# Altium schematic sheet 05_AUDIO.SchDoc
size A2; ApprovedBy: DNP; CheckedBy: DNP; Author: DNP; CompanyName: Google LLC; DrawnBy: DNP; Engineer: Bangfei/Michael/Leo; Organization: Google LLC; Address1: 1600 Amphitheatre Parkway; Address2: Mountain View, CA 94043; Address3: DNP; Address4: DNP; DocumentNumber: DNP; Revision: PVT; SheetNumber: 5; SheetTotal: 11; VersionControl_RevNumber: DNP; IsUserConfigurable: DNP
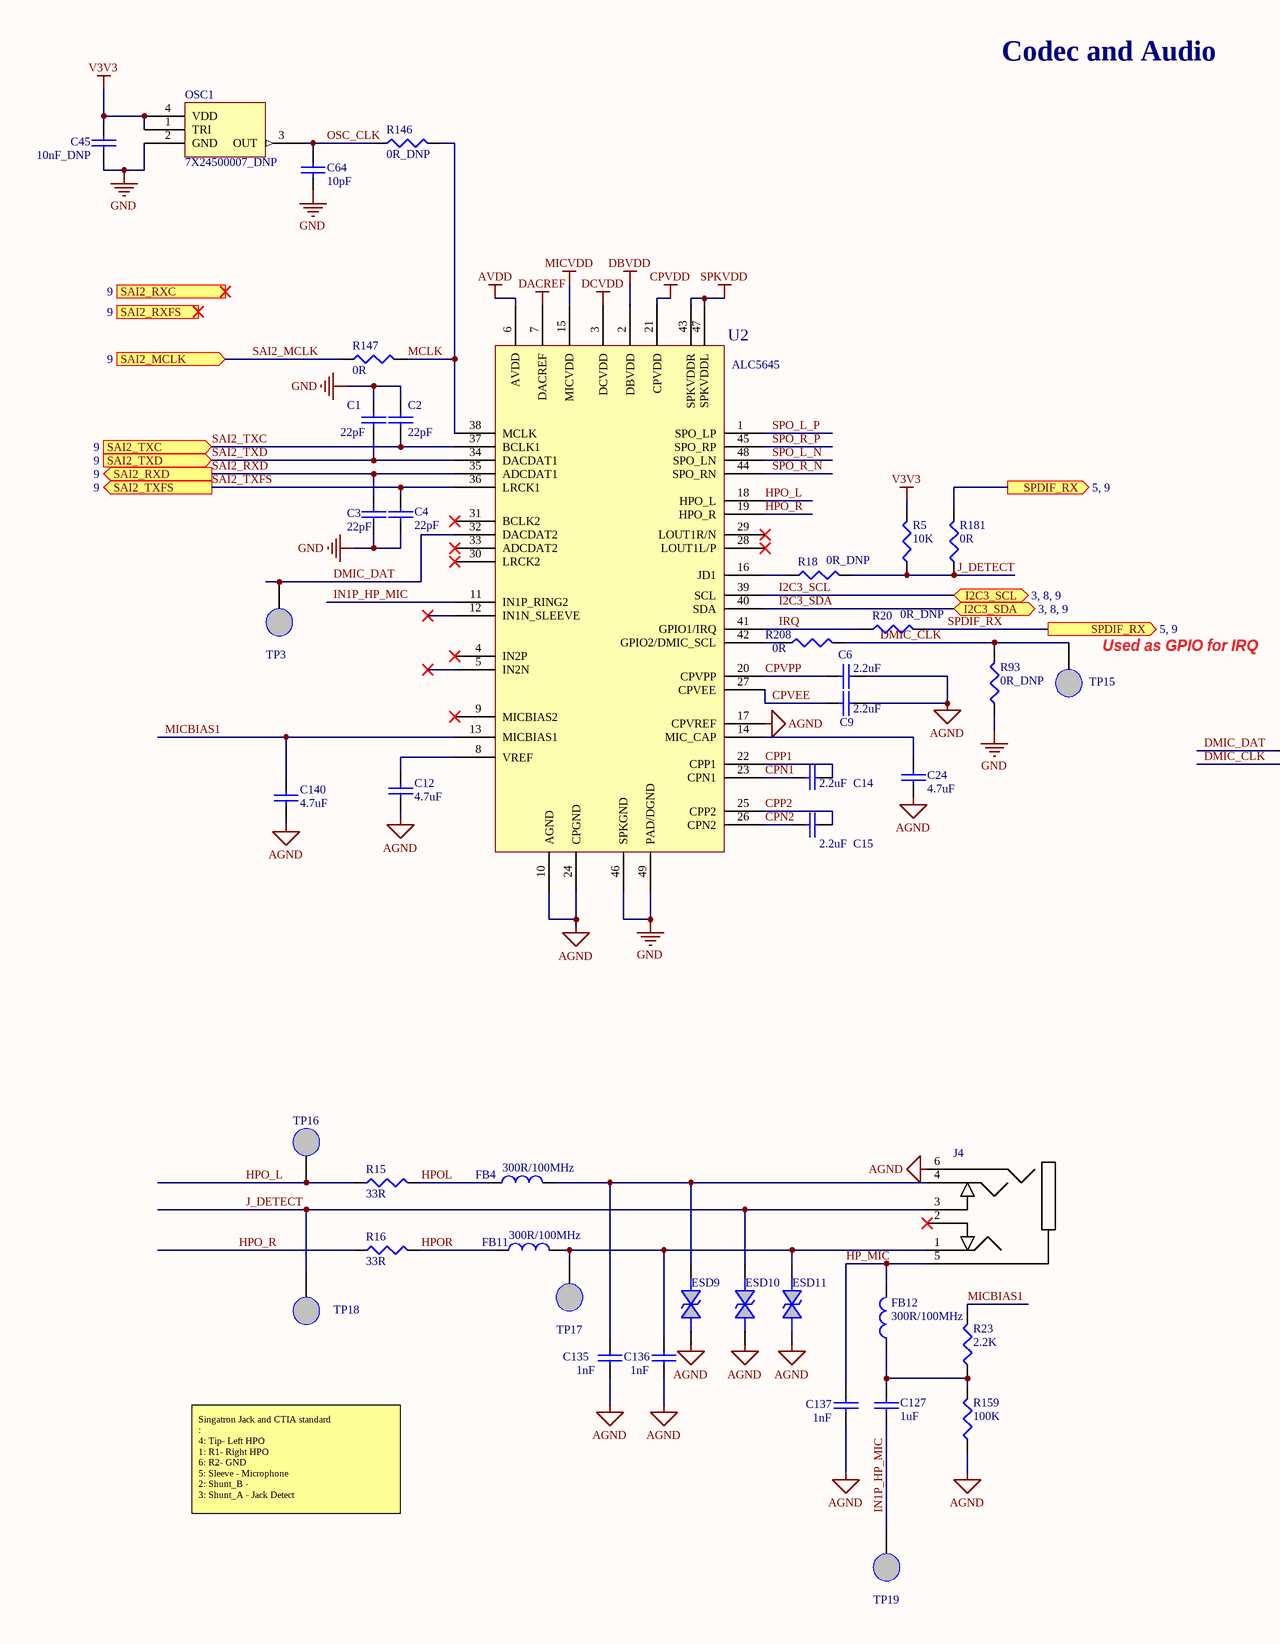
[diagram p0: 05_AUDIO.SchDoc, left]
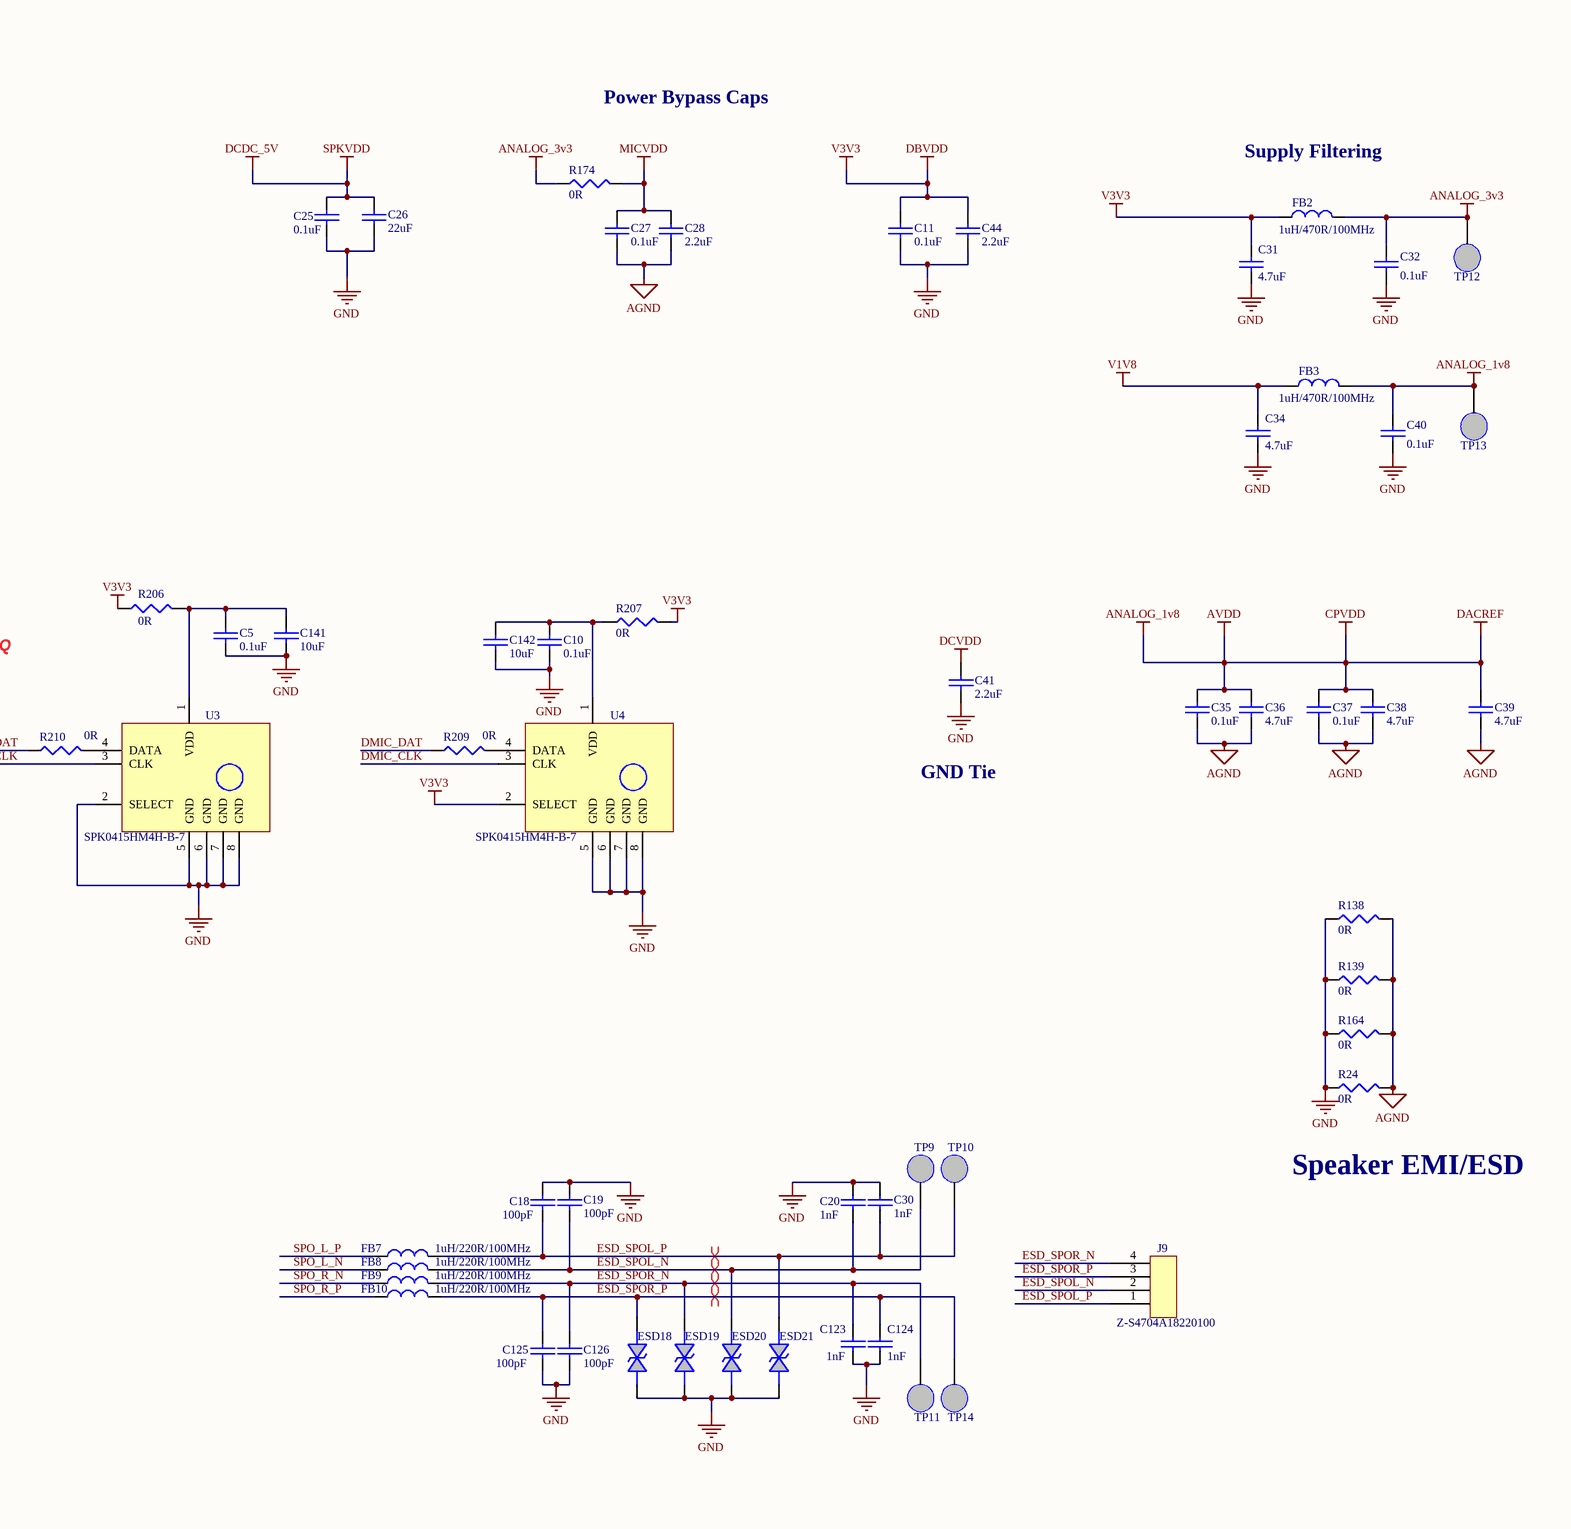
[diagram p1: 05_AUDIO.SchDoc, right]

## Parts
C1  value 22pF  [0201]  (hidden comment: 22pF/6.3V)
C2  value 22pF  [0201]  (hidden comment: 22pF/6.3V)
C3  value 22pF  [0201]  (hidden comment: 22pF/6.3V)
C4  value 22pF  [0201]  (hidden comment: 22pF/6.3V)
C5  value 0.1uF  [0201]  (hidden comment: 0.1uF/10V)
C6  value 2.2uF  [0201]  (hidden comment: 2.2uF/6.3V)
C9  value 2.2uF  [0201]  (hidden comment: 2.2uF/6.3V)
C10  value 0.1uF  [0201]  (hidden comment: 0.1uF/10V)
C11  value 0.1uF  [0201]  (hidden comment: 0.1uF/10V)
C12  value 4.7uF  [0402]  (hidden comment: 4.7uF/10V)
C14  value 2.2uF  [0201]  (hidden comment: 2.2uF/6.3V)
C15  value 2.2uF  [0201]  (hidden comment: 2.2uF/6.3V)
C18  value 100pF  [0201]  (hidden comment: 100pF/25V)
C19  value 100pF  [0201]  (hidden comment: 100pF/25V)
C20  value 1nF  [0201]  (hidden comment: 1nF/25V)
C24  value 4.7uF  [0402]  (hidden comment: 4.7uF/10V)
C25  value 0.1uF  [0402]  (hidden comment: 0.1uF/16V)
C26  value 22uF  [0603]  (hidden comment: 10uF/10V)
C27  value 0.1uF  [0201]  (hidden comment: 0.1uF/10V)
C28  value 2.2uF  [0201]  (hidden comment: 2.2uF/6.3V)
C30  value 1nF  [0201]  (hidden comment: 1nF/25V)
C31  value 4.7uF  [0402]  (hidden comment: 4.7uF/10V)
C32  value 0.1uF  [0603]  (hidden comment: 0.1uF/10V)
C34  value 4.7uF  [0402]  (hidden comment: 4.7uF/10V)
C35  value 0.1uF  [0201]  (hidden comment: 0.1uF/10V)
C36  value 4.7uF  [0402]  (hidden comment: 4.7uF/10V)
C37  value 0.1uF  [0201]  (hidden comment: 0.1uF/10V)
C38  value 4.7uF  [0402]  (hidden comment: 4.7uF/10V)
C39  value 4.7uF  [0402]  (hidden comment: 4.7uF/10V)
C40  value 0.1uF  [0402]  (hidden comment: 0.1uF/16V)
C41  value 2.2uF  [0201]  (hidden comment: 2.2uF/6.3V)
C44  value 2.2uF  [0201]  (hidden comment: 2.2uF/6.3V)
C45  10nF_DNP  [0201]
C64  value 10pF  [0201]  (hidden comment: 10pF/25V)
C123  value 1nF  [0201]  (hidden comment: 1nF/25V)
C124  value 1nF  [0201]  (hidden comment: 1nF/25V)
C125  value 100pF  [0201]  (hidden comment: 100pF/25V)
C126  value 100pF  [0201]  (hidden comment: 100pF/25V)
C127  value 1uF  [0402]  (hidden comment: 1uF/6.3V)
C135  value 1nF  [0201]  (hidden comment: 1nF/25V)
C136  value 1nF  [0201]  (hidden comment: 1nF/25V)
C137  value 1nF  [0201]  (hidden comment: 1nF/25V)
C140  value 4.7uF  [0402]  (hidden comment: 4.7uF/10V)
C141  value 10uF  [0402]  (hidden comment: 10uF/10V)
C142  value 10uF  [0402]  (hidden comment: 10uF/10V)
ESD9  3.5pF/5V  [0201]  (value not drawn)
ESD10  3.5pF/5V  [0201]  (value not drawn)
ESD11  3.5pF/5V  [0201]  (value not drawn)
ESD18  3.5pF/5V  [0201]  (value not drawn)
ESD19  3.5pF/5V  [0201]  (value not drawn)
ESD20  3.5pF/5V  [0201]  (value not drawn)
ESD21  3.5pF/5V  [0201]  (value not drawn)
FB2  1uH/470R/100MHz  [0603]
FB3  1uH/470R/100MHz  [0603]
FB4  300R/100MHz  [0402]
FB7  1uH/220R/100MHz  [0603]
FB8  1uH/220R/100MHz  [0603]
FB9  1uH/220R/100MHz  [0603]
FB10  1uH/220R/100MHz  [0603]
FB11  300R/100MHz  [0402]
FB12  300R/100MHz  [0402]
J4  CONN_2SJ2296-000111  [AUDIO-2SJ2296-000111]  (value not drawn)
J9  Z-S4704A18220100  [SIP4-2_54-S4704A18220100]
OSC1  7X24500007_DNP  [4-SMD-OSC]
R5  10K  [0201]
R15  33R  [0402]
R16  33R  [0402]
R18  0R_DNP  [0201]
R20  0R_DNP  [0201]
R23  2.2K  [0201]
R24  0R  [0201]
R93  0R_DNP  [0201]
R138  0R  [0201]
R139  0R  [0201]
R146  0R_DNP  [0201]
R147  0R  [0201]
R159  100K  [0402]
R164  0R  [0201]
R174  0R  [0402]
R181  0R  [0201]
R206  0R  [0201]
R207  0R  [0201]
R208  0R  [0201]
R209  0R  [0201]
R210  0R  [0201]
TP3  TP NM  [TP_SMD]  (value not drawn)  (no BOM)
TP9  TP NM  [TP_SMD]  (value not drawn)  (no BOM)
TP10  TP NM  [TP_SMD]  (value not drawn)  (no BOM)
TP11  TP NM  [TP_SMD]  (value not drawn)  (no BOM)
TP12  TP NM  [TP_SMD]  (value not drawn)  (no BOM)
TP13  TP NM  [TP_SMD]  (value not drawn)  (no BOM)
TP14  TP NM  [TP_SMD]  (value not drawn)  (no BOM)
TP15  TP NM  [TP_SMD]  (value not drawn)  (no BOM)
TP16  TP NM  [TP_SMD]  (value not drawn)  (no BOM)
TP17  TP NM  [TP_SMD]  (value not drawn)  (no BOM)
TP18  TP NM  [TP_SMD]  (value not drawn)  (no BOM)
TP19  TP NM  [TP_SMD]  (value not drawn)  (no BOM)
U2  ALC5645  [CODEC_ALC5645]
U3  SPK0415HM4H-B-7  [Microphone_SPK0415HM4H-B-7]
U4  SPK0415HM4H-B-7  [Microphone_SPK0415HM4H-B-7]

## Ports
I2C3_SCL (bidir, see 3, 8, 9), I2C3_SDA (bidir, see 3, 8, 9), SAI2_MCLK (in, see 9), SAI2_RXC (in, see 9), SAI2_RXD (out, see 9), SAI2_RXFS (in, see 9), SAI2_TXC (in, see 9), SAI2_TXD (in, see 9), SAI2_TXFS (out, see 9), SPDIF_RX (out, see 5, 9)

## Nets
AGND: C6.2 C9.2 C12.2 C24.1 C27.2 C28.2 C35.2 C36.2 C37.2 C38.2 C39.2 C135.1 C136.1 C137.1 C140.2 ESD9.1 ESD10.1 ESD11.1 J4.6(RING_B) R24.2 R138.2 R139.2 R159.1 R164.2 U2.10(AGND) U2.17(CPVREF) U2.24(CPGND)
ANALOG_1v8: C35.1 C36.1 C37.1 C38.1 C39.1 C40.1 FB3.2 TP13.1 U2.6(AVDD) U2.7(DACREF) U2.21(CPVDD)  [also labelled AVDD, CPVDD, DACREF]
ANALOG_3v3: C32.1 FB2.2 R174.1 TP12.1
DBVDD: C11.1 C31.1 C44.1 C45.1 FB2.1 OSC1.1(TRI) OSC1.4(VDD) R5.2 R206.1 R207.2 U2.2(DBVDD) U4.2(SELECT)  [also labelled V3V3]
DCDC_5V: C25.1 C26.1 U2.43(SPKVDDR) U2.47(SPKVDDL)  [also labelled SPKVDD]
DCVDD: C41.1 U2.3(DCVDD)
GND: C1.1 C2.1 C3.2 C4.2 C5.2 C10.2 C11.2 C18.1 C19.1 C20.2 C25.2 C26.2 C30.2 C31.2 C32.2 C34.2 C40.2 C41.2 C44.2 C45.2 C64.2 C123.1 C124.1 C125.2 C126.2 C141.2 C142.2 ESD18.1 ESD19.1 ESD20.1 ESD21.1 OSC1.2(GND) R24.1 R93.1 R138.1 R139.1 R164.1 U2.46(SPKGND) U2.49(PAD/DGND) U3.2(SELECT) U3.5(GND) U3.6(GND) U3.7(GND) U3.8(GND) U4.5(GND) U4.6(GND) U4.7(GND) U4.8(GND)
MICVDD: C27.1 C28.1 R174.2 U2.15(MICVDD)
V1V8: C34.1 FB3.1
CPN1: C14.1 U2.23(CPN1)
CPN2: C15.1 U2.26(CPN2)
CPP1: C14.2 U2.22(CPP1)
CPP2: C15.2 U2.25(CPP2)
CPVEE: C9.1 U2.27(CPVEE)
CPVPP: C6.1 U2.20(CPVPP)
DMIC_CLK: R93.2 R208.2 TP15.1 U3.3(CLK) U4.3(CLK)
DMIC_DAT: R209.1 R210.1 TP3.1 U2.32(DACDAT2)
ESD_SPOL_N: C19.2 C20.1 ESD20.2 FB8.2 J9.2 TP9.1
ESD_SPOL_P: C18.2 C30.1 ESD21.2 FB7.2 J9.1 TP10.1
ESD_SPOR_N: C123.2 C126.1 ESD19.2 FB9.2 J9.4 TP11.1
ESD_SPOR_P: C124.2 C125.1 ESD18.2 FB10.2 J9.3 TP14.1
HP_MIC: C137.2 FB12.2 J4.5(SLEEVE)
HPO_L: R15.1 TP16.1 U2.18(HPO_L)
HPO_R: R16.1 U2.19(HPO_R)
HPOL: FB4.1 R15.2
HPOR: FB11.1 R16.2
I2C3_SCL: U2.39(SCL) ; port I2C3_SCL
I2C3_SDA: U2.40(SDA) ; port I2C3_SDA
IN1P_HP_MIC: C127.2 TP19.1 U2.11(IN1P_RING2)
IRQ: R20.1 U2.41(GPIO1/IRQ)
J_DETECT: ESD10.2 J4.3(SHUNT_A) R5.1 R18.2 R181.1 TP18.1
MCLK: R146.2 R147.2 U2.38(MCLK)
MICBIAS1: C140.1 R23.2 U2.13(MICBIAS1)
OSC_CLK: C64.1 OSC1.3(OUT) R146.1
SAI2_MCLK: R147.1 ; port SAI2_MCLK
SAI2_RXD: C3.1 U2.35(ADCDAT1) ; port SAI2_RXD
SAI2_TXC: C2.2 U2.37(BCLK1) ; port SAI2_TXC
SAI2_TXD: C1.2 U2.34(DACDAT1) ; port SAI2_TXD
SAI2_TXFS: C4.1 U2.36(LRCK1) ; port SAI2_TXFS
SPDIF_RX: R20.2 R181.2 ; port SPDIF_RX
SPO_L_N: FB8.1 U2.48(SPO_LN)
SPO_L_P: FB7.1 U2.1(SPO_LP)
SPO_R_N: FB9.1 U2.44(SPO_RN)
SPO_R_P: FB10.1 U2.45(SPO_RP)
NetC5_1: C5.1 C141.1 R206.2 U3.1(VDD)
NetC10_1: C10.1 C142.1 R207.1 U4.1(VDD)
NetC12_1: C12.1 U2.8(VREF)
NetC24_2: C24.2 U2.14(MIC_CAP)
NetC127_1: C127.1 FB12.1 R23.1 R159.2
NetC135_2: C135.2 ESD9.2 FB4.2 J4.4(TIP_SPRING)
NetC136_2: C136.2 ESD11.2 FB11.2 J4.1(RING_A) TP17.1
NetR18_1: R18.1 U2.16(JD1)
NetR208_1: R208.1 U2.42(GPIO2/DMIC_SCL)
NetR209_2: R209.2 U4.4(DATA)
NetR210_2: R210.2 U3.4(DATA)

Not connected (* = marked no-connect by the designer): J4 2(SHUNT_B)*; U2 4(IN2P)* 5(IN2N)* 9(MICBIAS2)* 12(IN1N_SLEEVE)* 28(LOUT1L/P)* 29(LOUT1R/N)* 30(LRCK2)* 31(BCLK2)* 33(ADCDAT2)*

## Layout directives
differential pair: ESD_SPOL_N, ESD_SPOL_P, ESD_SPOR_N, ESD_SPOR_P

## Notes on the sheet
- Codec and Audio
- Power Bypass Caps
- Supply Filtering
- (near TP15) Used as GPIO for IRQ
- GND Tie
- Speaker EMI/ESD
- Singatron Jack and CTIA standard
  :
  4: Tip- Left HPO
  1: R1- Right HPO
  6: R2- GND
  5: Sleeve - Microphone
  2: Shunt_B -
  3: Shunt_A - Jack Detect
  Shunt A (pin #3) is normally closed with pin #4; Shunt B (pin #2) is normally closed with pin #1.
  When plug inserted, Shunt A (pin #3) is open from pin # 4 & Shunt B (pin #2) is open from pin #1.

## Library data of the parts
C1-C4 = CAP_0201_22pF: CAP CER 22pF 6.3V 2% C0G NP0 0201; MPN: GJM0335C0J220GB01D; QCI MPN: GRM0335C1H220G; QPN: CH0226G0E00; QPN Description: CAP CHIP 22PF 50V(+-2%,COG,0201); Function Code: ADO
C5 C10 C11 C27 C35 C37 = CAP_0201_0.1uF: CAP CER 0.1UF 10V 10% X5R 0201; MPN: C0603X5R1A104K030BC; QCI MPN: GRM033R61A104K; QPN: CH4102K9E00; QPN Description: CAP CHIP 0.1U 10V(+-10%,X5R,0201); Function Code: ADO
C6 C9 C14 C15 C28 C41 C44 = CAP_0201_2.2uF: CAP CER 2.2uF 6.3V 20% X5R 0201; MPN: GRM033R60J225ME15D; QCI MPN: GRM033R60J225M; QPN: CH5221M9E00; QPN Description: CAP CHIP 2.2UF 6.3V(+-20%,X5R,0201); Function Code: ADO
C12 C24 C36 C38 C39 C140 = CAP_0201_4.7uF: CAP CER 4.7UF 10V 20% X5R 0402; MPN: C1005X5R1A475M050BC; QCI MPN: GRM155R61A475M; QPN: CH5472M9B01; QPN Description: CAP CHIP 4.7U 10V(+-20%,X5R,0402); Function Code: ADO
C18 C19 C125 C126 = CAP_0201_100pF: CAP CER 100PF 25V X7R 0201; MPN: GRM033R71E101KA01D; QCI MPN: GRM033R71E101K; QPN: CH1104K1E01; QPN Description: CAP CHIP 100PF 25V(+-10%,X7R,0201); Function Code: SPK
C20 C30 C123 C124 = CAP_0201_1.0nF: CAP CER 1nF 25V 10% X7R 0201; MPN: GRM033R71E102KA01D; QCI MPN: GRM033R71E102K; QPN: CH2104K1E00; QPN Description: CAP CHIP 1000P 25V(+-10%,X7R,0201); Function Code: SPK
C25 C40 = CAP_0402_0.1uF: CAP CER 0.1uF 16V 10% X7R 0402; MPN: C0402C104K4RACTU; QCI MPN: GRM155R71C104K; QPN: CH4103K1B18; QPN Description: CAP CHIP 0.1U 16V(10%,X7R,0402); Function Code: ADO
C26 = CAP_0603_22uF: CAP CER 22UF 6.3V 10% X5R 0603; MPN: CL10A226KQ8NRNE; QCI MPN: GRM188R61A106M; QPN: CH6102M9900; QPN Description: CAP CHIP 10U 10V(+-20%,X5R,0603); Function Code: USB
C31 C34 = CAP_0402_4.7uF: CAP CER 4.7UF 10V 20% X5R 0402; MPN: C1005X5R1A475M050BC; QCI MPN: GRM155R61A475M; QPN: CH5472M9B01; QPN Description: CAP CHIP 4.7U 10V(+-20%,X5R,0402); Function Code: ADO
C32 = CAP_0603_0.1uF: CAP CER 0.1UF 10V 10% X5R 0603; MPN: GRM188R71C104M; QCI MPN: 0603B104K100CT; QPN: CH4102K1900; QPN Description: CAP CHIP 0.1UF 10V(+-10%,X7R,0603); Function Code: ADO
C45 = CAP_0201_10nF: CAP CER 0.01UF 10V 10% X5R 0201; MPN: GRM033R61A103KA01D; QCI MPN: GRM033R71A103K; DNP: V; QPN: CH3102K1E01; QPN Description: CAP CHIP 0.01UF 10V(10%,X7R,0201); Function Code: ADO
C64 = CAP_0201_10pF_HF: CAP CER 10PF 25V 5% C0H 0201; MPN: GJM0336C1E100JB01D; QCI MPN: GRM0335C1E100J; QPN: CH0104J0E05; QPN Description: CAP CHIP 10P 25V(+-5%,COG,0201); Function Code: ADO
C127 = CAP_0402_1.0uF: CAP CER 1.0UF 6.3V 10% X5R 0402; MPN: C0603X5R0J105M030BC; QCI MPN: GRM155R70J105K; QPN: CH5101K1B01; QPN Description: CAP CHIP 1U,6.3V(+-10%,X7R,0402); Function Code: AMJ
C135-C137 = CAP_0201_1.0nF: CAP CER 1nF 25V 10% X7R 0201; MPN: GRM033R71E102KA01D; QCI MPN: GRM033R71E102K; QPN: CH2104K1E00; QPN Description: CAP CHIP 1000P 25V(+-10%,X7R,0201); Function Code: AMJ
C141 C142 = CAP_0402_10uF: CAP CER 10UF 10V 20% X5R 0402; MPN: CL05A106MP5NUNC; QCI MPN: GRM155R61A106M; QPN: CH6102M9B00; QPN Description: CAP CHIP 10U 10V (+-20%, X5R, 0402)'; Function Code: LAN
ESD9-ESD11 = DIODE BI-DIR TRIG: DIODE TVS 15kV 10V 50A 8pF SMT RoHS; MPN: DESD5V0V1BCSP-7; QPN: BC5V0V1BZ02; QPN Description: DIODE ESD SMD DESD5V0V1BCSP-7 6V,DSN0603; Function Code: AMJ
ESD18-ESD21 = DIODE BI-DIR TRIG: DIODE TVS 15kV 10V 50A 8pF SMT RoHS; MPN: DESD5V0V1BCSP-7; QPN: BC5V0V1BZ02; QPN Description: DIODE ESD SMD DESD5V0V1BCSP-7 6V,DSN0603; Function Code: SPK
FB2 FB3 = INDUCTOR_BLM18PG471SN1: FERRITE CHIP 470 OHM 1.0A 0603; QCI MPN: BLM18PG471SN1D; QPN: CX8PG471000; QPN Description: EMI FILTER BLM18PG471SN1D(470,1000MA); Function Code: ADO
FB4 FB11 FB12 = INDUCTOR_BLM18EG221SN1D: EMI FILTER FCM1005KF-301T03 (300,300MA); Value: 1uH; QPN: CX301T03000; Function Code: AMJ
FB7-FB10 = INDUCTOR_BLM18EG221SN1D: FERRITE CHIP 220 OHM 2.0A 0603; Value: 1uH; QPN: CX8EG221011; QPN Description: EMI FILTER BLM18EG221SN1D(220,2A); Function Code: SPK
J4 = CONN_2SJ2296-000111: CONN AUDIO JACK 3.5MM 6COND SMD; QPN: DFTJ06FR320; QPN Description: CONN SMD PHONE JACK 6P FR(H4.5); Function Code: AMJ
J9 = CONN_TERMINAL_4POS_PHOENIX: CONN TERM BLOCK 2.54MM 4POS PCB; QPN: DFHS04FR969; QPN Description: CONN DIP HOUSING 4P 1R FR(P2.54,H8.5); Function Code: SPK
OSC1 = OSC_7X24500007: 24.576MHz SINE Oscillator Surface Mount 3.3V 13mA Enable/Disable; DNP: V; Function Code: ADO
R5 = R_0201_10K: RES SMD 10K OHM JUMPER 1/20W  0201; MPN: ERJ-1GEF103C; QCI MPN: RC0201JR-1310KL; QPN: CS31001JE16; QPN Description: RES CHIP 10K 1/20W +-5%(0201); Function Code: ADO
R15 R16 = R_0402_33: RES SMD 33 OHM 1% 1/10W 0402; MPN: RC0402FR-0733R; QPN: CS03302FB01; QPN Description: RES CHIP 33 1/16W +-1%(0402); Function Code: AMJ
R18 R20 R93 R146 = R_0201_0: RES SMD 0.0OHM JUMPER 1/20W 0201; MPN: ERJ-1GN0R00C; QCI MPN: RC0201JR-130RL; DNP: V; QPN: CS00001JE18; QPN Description: RES CHIP 0(1/20W,+-5%,0201); Function Code: ADO
R23 = R_0201_2.2K: RES SMD 2.2K OHM 1% 1/20W 0201; MPN: ERJ-1GEF2201C; QCI MPN: RC0201FR-072K2L; QPN: CS22201FE04; QPN Description: RES CHIP 2.2K 1/20W +-1%(0201); Function Code: AMJ
R24 R138 R139 R164 R206-R210 = R_0805_0: RES SMD 0.0OHM JUMPER 1/20W 0201; MPN: ERJ-1GN0R00C; QCI MPN: RC0201JR-130RL; QPN: CS00001JE18; QPN Description: RES CHIP 0(1/20W,+-5%,0201); Function Code: SPK
R147 R181 = R_0201_0: RES SMD 0.0OHM JUMPER 1/20W 0201; MPN: ERJ-1GN0R00C; QCI MPN: RC0201JR-130RL; QPN: CS00001JE18; QPN Description: RES CHIP 0(1/20W,+-5%,0201); Function Code: ADO
R159 = R_0402_1.6k: RES CHIP 100K 1/16W 5%(0402); MPN: YAG3045TR-ND; QCI MPN: RC0402JR-7D100KL; QPN: CS41002JB20; Function Code: AMJ
R174 = R_0402_0: RES SMD 0.0 OHM JUMPER 1/10W  0402; MPN: ERJ-2GE0R00X; QCI MPN: RC0402FR-070RL; QPN: CS00002FB00; QPN Description: RES CHIP 0 1/16W +-1%(0402); Function Code: DBG
TP3 TP9-TP19 = TP: TEST POIN
U2 = ALC5645: Multi-Channel Audio Hub/CODEC and SounzReal Digital Sound Effect; QCI MPN: ALC5645-CGT; QPN: AL005645000; QPN Description: IC OTHER(48P) ALC5645-CGT(QFN); Function Code: ADO
U3 U4 = Microphone_SPK0415HM4H-B-7: Microphone MEMS, Digital PDM OMNI -26dB; QPN: DN0415HM000; QPN Description: MICPHONE SPK0415HM4H-B-7; Function Code: ADO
